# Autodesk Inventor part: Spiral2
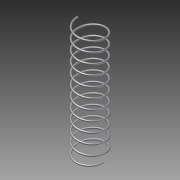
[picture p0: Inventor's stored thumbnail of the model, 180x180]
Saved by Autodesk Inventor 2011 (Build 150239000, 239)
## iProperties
Created: 2014-02
Part Number: Spiral2
Document SubType Name: Modeling
Designer: Evgeny
Density: 1 g/cm^3
Author: Evgeny
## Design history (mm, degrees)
sketch "Эскиз2"
  geometry: L1 (0, 0)-(0, 24); C1 r 1.5 at (-24.955, 0)
  constraints: 2 end point, 1 centre point, 1 vertical
  dimensions: "d19" = 3 diameter of C1; "d20" = 24.955 distance from line of C1.centre L1
feature "Пружина2" sketch "Эскиз2" pitch "d21" = 18.2; turns "d23" = 11.25; dims "d22" = 10, "d24" = 0, angle "d25" = 5 deg, angle "d26" = 90 deg, "d27" = 0, "d28" = 0
node "Твердое тело2"
